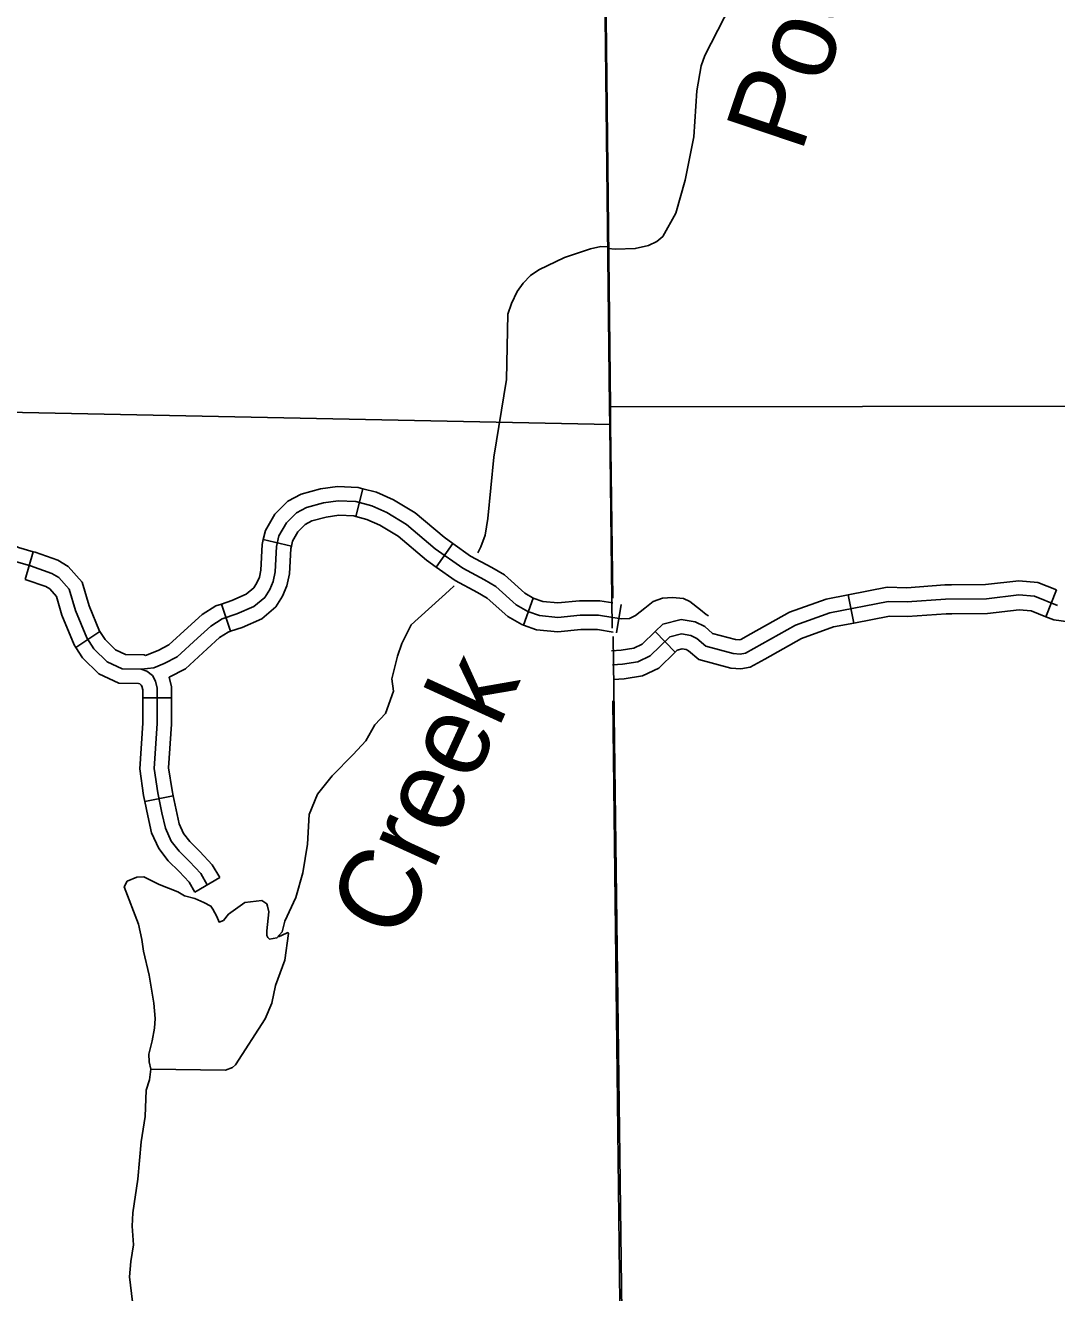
# Model space of a CAD drawing. Extents: x 1373862 to 1376999, y 1168398 to 1170455.
# Drawn here: x 1375499.6 to 1375607, y 1169230.9 to 1169362.9 of the extents above; entities that cross this region are included whole.
import ezdxf

# ---------------------------------------------------------------- set-up
doc = ezdxf.new("R2010")
doc.units = 0
for name, color, linetype in [('Level 2', 7, 'Continuous'), ('Level 32', 7, 'Continuous'), ('Level 35', 7, 'Continuous'), ('Level 45', 7, 'Continuous'), ('Level 5', 7, 'Continuous')]:
    doc.layers.add(name, color=color, linetype=linetype)

msp = doc.modelspace()

# ---------------------------------------------------------------- linework, layer by layer
at = {"layer": 'Level 2'}
for points in [[(1375559.39, 1169426.01), (1375560.53, 1169323.17), (1375560.52, 1169321.29), (1375560.75, 1169303.22)], [(1375559.85, 1169373.12), (1375560.43, 1169323.13), (1375560.44, 1169321.15), (1375560.68, 1169300.07)], [(1375560.8, 1169299.22), (1375561.85, 1169218.06), (1375561.86, 1169216.25), (1375562.18, 1169170.5)], [(1375560.77, 1169292.5), (1375561.64, 1169217.86), (1375561.7, 1169216.02)]]:
    msp.add_lwpolyline(points, dxfattribs=at)
at = {"layer": 'Level 32'}
for p, q in [((1375533.99, 1169311.71), (1375534.75, 1169314.61)), ((1375527.29, 1169308.64), (1375524.37, 1169309.31)), ((1375542.38, 1169306.45), (1375544.12, 1169308.89)), ((1375500.42, 1169308.04), (1375499.59, 1169305.16)), ((1375551.47, 1169300.39), (1375552.48, 1169303.21)), ((1375520.96, 1169299.76), (1375520.01, 1169302.6)), ((1375561.64, 1169302.56), (1375561.16, 1169299.6)), ((1375507.36, 1169299.72), (1375504.84, 1169298.08)), ((1375514.81, 1169292.84), (1375511.81, 1169292.84)), ((1375514.98, 1169282.63), (1375512.04, 1169282.02)), ((1375519.83, 1169274.12), (1375517.25, 1169272.59))]:
    msp.add_line(p, q, dxfattribs=at)
for points in [[(1375524.37, 1169309.31), (1375524.59, 1169310.26), (1375525.58, 1169311.97), (1375526.91, 1169313.3), (1375528.3, 1169314.05), (1375530.33, 1169314.6), (1375532.08, 1169314.85), (1375534.24, 1169314.75), (1375534.75, 1169314.61)], [(1375534.75, 1169314.61), (1375536.16, 1169314.24), (1375537.91, 1169313.46), (1375540.17, 1169312.1), (1375543.2, 1169309.55), (1375544.12, 1169308.89)], [(1375511.66, 1169295.81), (1375512.96, 1169295.97), (1375514.05, 1169296.4), (1375515.39, 1169297.1), (1375517.51, 1169299.05), (1375518.9, 1169300.3), (1375520.07, 1169301.04), (1375521.62, 1169301.56), (1375523.4, 1169302.34), (1375524.53, 1169303.29), (1375525.05, 1169304.12), (1375525.39, 1169304.94), (1375525.61, 1169305.94), (1375525.74, 1169308.58), (1375526, 1169309.7), (1375526.78, 1169311.05), (1375527.82, 1169312.09), (1375528.86, 1169312.65), (1375530.63, 1169313.13), (1375532.15, 1169313.34), (1375534.01, 1169313.26), (1375535.66, 1169312.82), (1375537.22, 1169312.13), (1375539.29, 1169310.87), (1375542.28, 1169308.36), (1375545.14, 1169306.33), (1375547.41, 1169305.11), (1375548.58, 1169304.42), (1375550.71, 1169302.51), (1375551.92, 1169301.82), (1375553.13, 1169301.39), (1375555.04, 1169301.21), (1375557.37, 1169301.43), (1375559.28, 1169301.43), (1375560.78, 1169301.18)], [(1375500.42, 1169308.04), (1375498.88, 1169308.48), (1375495.38, 1169310.25), (1375491.76, 1169311.36), (1375490.89, 1169311.8)], [(1375527.29, 1169308.64), (1375527.41, 1169309.15), (1375527.98, 1169310.13), (1375528.72, 1169310.87), (1375529.42, 1169311.25), (1375530.93, 1169311.66), (1375532.22, 1169311.84), (1375533.78, 1169311.77), (1375533.99, 1169311.71)], [(1375533.99, 1169311.71), (1375535.16, 1169311.4), (1375536.52, 1169310.8), (1375538.42, 1169309.65), (1375541.36, 1169307.17), (1375542.38, 1169306.45)], [(1375520.01, 1169302.6), (1375521.08, 1169302.96), (1375522.6, 1169303.62), (1375523.38, 1169304.29), (1375523.71, 1169304.81), (1375523.96, 1169305.39), (1375524.12, 1169306.13), (1375524.25, 1169308.79), (1375524.37, 1169309.31)], [(1375520.96, 1169299.76), (1375522.16, 1169300.16), (1375524.2, 1169301.05), (1375525.67, 1169302.3), (1375526.38, 1169303.42), (1375526.83, 1169304.48), (1375527.1, 1169305.74), (1375527.23, 1169308.37), (1375527.29, 1169308.64)], [(1375544.12, 1169308.89), (1375545.93, 1169307.6), (1375548.15, 1169306.42), (1375549.48, 1169305.63), (1375551.59, 1169303.73), (1375552.55, 1169303.19), (1375552.48, 1169303.21)], [(1375507.36, 1169299.72), (1375507.33, 1169299.76), (1375506.24, 1169302.42), (1375505.52, 1169304.88), (1375504.05, 1169306.52), (1375502.99, 1169307.15), (1375500.6, 1169307.99), (1375500.42, 1169308.04)], [(1375518.54, 1169273.35), (1375517.85, 1169274.52), (1375516.68, 1169275.78), (1375515.6, 1169276.86), (1375514.77, 1169277.9), (1375514.17, 1169279.24), (1375513.82, 1169280.85), (1375513.39, 1169282.93), (1375513.01, 1169285.48), (1375513.31, 1169290.14), (1375513.31, 1169293.82), (1375513.14, 1169294.56), (1375512.83, 1169295.16), (1375512.23, 1169295.6), (1375511.66, 1169295.81), (1375509.67, 1169295.86), (1375508.11, 1169296.59), (1375506.73, 1169297.94), (1375505.99, 1169299.06), (1375504.82, 1169301.92), (1375504.17, 1169304.13), (1375503.09, 1169305.35), (1375502.35, 1169305.78), (1375500.14, 1169306.56), (1375498.33, 1169307.08)], [(1375542.38, 1169306.45), (1375544.35, 1169305.05), (1375546.68, 1169303.8), (1375547.69, 1169303.2), (1375549.82, 1169301.29), (1375551.29, 1169300.45), (1375551.47, 1169300.39)], [(1375504.84, 1169298.08), (1375504.66, 1169298.36), (1375503.4, 1169301.43), (1375502.83, 1169303.39), (1375502.13, 1169304.17), (1375501.72, 1169304.41), (1375499.69, 1169305.13), (1375499.59, 1169305.16)], [(1375552.48, 1169303.21), (1375553.46, 1169302.86), (1375555.03, 1169302.72), (1375557.31, 1169302.93), (1375559.4, 1169302.93), (1375560.76, 1169302.71)], [(1375570.72, 1169301.37), (1375570.49, 1169301.52), (1375569.88, 1169301.99), (1375568.8, 1169302.86), (1375568.11, 1169303.16), (1375566.99, 1169303.29), (1375565.95, 1169303.21), (1375564.95, 1169302.86), (1375564.09, 1169302.17), (1375563.13, 1169301.39), (1375562.49, 1169301.08), (1375561.66, 1169301.04), (1375560.78, 1169301.18)], [(1375512.12, 1169297.25), (1375513.42, 1169297.77), (1375514.52, 1169298.34), (1375516.5, 1169300.15), (1375517.99, 1169301.5), (1375519.42, 1169302.4), (1375520.01, 1169302.6)], [(1375512.12, 1169297.25), (1375511.96, 1169297.31), (1375510.02, 1169297.35), (1375508.98, 1169297.84), (1375507.89, 1169298.9), (1375507.36, 1169299.72)], [(1375514.58, 1169294.99), (1375516.26, 1169295.86), (1375518.52, 1169297.94), (1375519.81, 1169299.1), (1375520.71, 1169299.67), (1375520.96, 1169299.76)], [(1375551.47, 1169300.39), (1375552.81, 1169299.91), (1375555.04, 1169299.71), (1375557.44, 1169299.93), (1375559.16, 1169299.93), (1375560.8, 1169299.66)], [(1375511.81, 1169292.84), (1375511.81, 1169293.65), (1375511.72, 1169294.04), (1375511.66, 1169294.16), (1375511.51, 1169294.27), (1375511.37, 1169294.32), (1375509.32, 1169294.36), (1375507.25, 1169295.34), (1375505.56, 1169296.98), (1375504.84, 1169298.08)], [(1375514.81, 1169292.84), (1375514.81, 1169293.99), (1375514.58, 1169294.99)], [(1375512.04, 1169282.02), (1375511.91, 1169282.66), (1375511.5, 1169285.42), (1375511.81, 1169290.19), (1375511.81, 1169292.84)], [(1375514.98, 1169282.63), (1375514.87, 1169283.19), (1375514.51, 1169285.55), (1375514.81, 1169290.09), (1375514.81, 1169292.84)], [(1375519.83, 1169274.12), (1375519.06, 1169275.43), (1375517.76, 1169276.82), (1375516.72, 1169277.86), (1375516.06, 1169278.69), (1375515.6, 1169279.72), (1375515.29, 1169281.16), (1375514.98, 1169282.63)], [(1375517.25, 1169272.59), (1375516.64, 1169273.62), (1375515.6, 1169274.74), (1375514.47, 1169275.86), (1375513.48, 1169277.12), (1375512.73, 1169278.77), (1375512.35, 1169280.54), (1375512.04, 1169282.02)]]:
    msp.add_lwpolyline(points, dxfattribs=at)
at = {"layer": 'Level 35'}
for points in [[(1375573.72, 1169366.31), (1375570.34, 1169359.74), (1375569.96, 1169358.65), (1375569.51, 1169356.05), (1375569.2, 1169351.25), (1375568.31, 1169346.75), (1375567.31, 1169343.32), (1375565.98, 1169340.89), (1375565.35, 1169340.35), (1375564.47, 1169339.95), (1375563.1, 1169339.62), (1375561.03, 1169339.55), (1375560.24, 1169339.61)], [(1375560.34, 1169339.79), (1375559.53, 1169339.85), (1375558.43, 1169339.6), (1375555.75, 1169338.7), (1375553.05, 1169337.4), (1375552.18, 1169336.8), (1375551.44, 1169336), (1375550.81, 1169335.14), (1375550.2, 1169333.89), (1375549.82, 1169332.78), (1375549.69, 1169325.99), (1375548.37, 1169317.9), (1375547.74, 1169311.51), (1375547.46, 1169309.78), (1375547.03, 1169308.55), (1375546.71, 1169307.92)], [(1375544.23, 1169304.51), (1375543.74, 1169304), (1375539.75, 1169300.42), (1375538.79, 1169298.48), (1375538.35, 1169297.16), (1375537.76, 1169294.82), (1375537.93, 1169293.51), (1375537.1, 1169291.18), (1375536, 1169290.01), (1375535.04, 1169288.35), (1375533.73, 1169286.91), (1375531.53, 1169284.71), (1375530.02, 1169282.78), (1375529.13, 1169280.67), (1375528.96, 1169277.6), (1375528.47, 1169274.6), (1375527.74, 1169272.02), (1375526.61, 1169269.57), (1375526.35, 1169268.44), (1375525.79, 1169267.82), (1375525.03, 1169267.71), (1375524.84, 1169267.86), (1375524.74, 1169268.06), (1375524.75, 1169268.56), (1375524.93, 1169270.55), (1375524.81, 1169271.13), (1375524.73, 1169271.37), (1375524.22, 1169271.72), (1375522.44, 1169271.52), (1375520.76, 1169270.3), (1375520.21, 1169269.63), (1375519.76, 1169269.48), (1375519.52, 1169270.05), (1375519.1, 1169270.81), (1375518.91, 1169271.14), (1375518.18, 1169271.5), (1375517.25, 1169271.93), (1375516.18, 1169272.21), (1375515.46, 1169272.63), (1375513.53, 1169273.39), (1375511.93, 1169274.18), (1375511.19, 1169274.14), (1375510.2, 1169273.72), (1375509.87, 1169273.15), (1375511.36, 1169269.25), (1375511.72, 1169267.65), (1375511.9, 1169266.46), (1375512.5, 1169263.96), (1375512.96, 1169261.04), (1375513.1, 1169259.44), (1375513.04, 1169258.42), (1375512.81, 1169257.09), (1375512.44, 1169255.72), (1375512.48, 1169254.92), (1375512.67, 1169254.14), (1375512.52, 1169253.05), (1375512.18, 1169251.98), (1375512.08, 1169249.21), (1375511.64, 1169246.59), (1375511.32, 1169242.71), (1375510.78, 1169239.19), (1375510.71, 1169237.81), (1375510.87, 1169235.85), (1375510.57, 1169234.11), (1375510.42, 1169232.53), (1375510.74, 1169229.93)], [(1375525.95, 1169267.93), (1375526.78, 1169268.33), (1375526.92, 1169268.37), (1375527, 1169268.29), (1375526.6, 1169265.49), (1375525.64, 1169262.87), (1375525.25, 1169261.03), (1375524.55, 1169259.39), (1375521.47, 1169254.61), (1375521.15, 1169254.34), (1375520.42, 1169254.05), (1375512.67, 1169254.14)]]:
    msp.add_lwpolyline(points, dxfattribs=at)
at = {"layer": 'Level 45'}
for p, q in [((1375585.28, 1169303.56), (1375585.85, 1169300.62)), ((1375606.98, 1169304.06), (1375605.87, 1169301.27)), ((1375565.18, 1169299.74), (1375567.27, 1169297.58))]:
    msp.add_line(p, q, dxfattribs=at)
for points in [[(1375596.03, 1169304.59), (1375595.35, 1169304.58), (1375591.38, 1169304.3), (1375589.33, 1169304.34), (1375585.28, 1169303.56)], [(1375606.98, 1169304.06), (1375605.02, 1169304.84), (1375603.03, 1169305.03), (1375599.58, 1169304.62), (1375596.03, 1169304.59)], [(1375607.08, 1169302.44), (1375604.67, 1169303.4), (1375603.05, 1169303.55), (1375599.68, 1169303.14), (1375595.41, 1169303.11), (1375591.42, 1169302.83), (1375589.45, 1169302.86), (1375583.35, 1169301.69), (1375579.78, 1169300.41), (1375574.57, 1169297.48), (1375574.03, 1169297.39), (1375573.31, 1169297.45), (1375570.45, 1169298.2), (1375569.51, 1169299.01), (1375568.89, 1169299.31), (1375567.93, 1169299.48), (1375566.7, 1169299.17), (1375564.67, 1169297.19), (1375563.38, 1169296.58), (1375561.78, 1169296.33), (1375560.73, 1169296.26)], [(1375585.28, 1169303.56), (1375582.97, 1169303.12), (1375579.17, 1169301.76), (1375575.12, 1169299.48)], [(1375605.87, 1169301.27), (1375604.31, 1169301.9), (1375603.07, 1169302.01), (1375599.77, 1169301.62), (1375596.05, 1169301.59)], [(1375575.12, 1169299.48), (1375574.08, 1169298.89), (1375573.97, 1169298.87), (1375573.55, 1169298.9), (1375571.15, 1169299.54), (1375570.33, 1169300.25), (1375569.35, 1169300.73), (1375567.87, 1169300.98), (1375565.96, 1169300.49), (1375565.18, 1169299.74)], [(1375585.85, 1169300.62), (1375583.76, 1169300.22), (1375580.42, 1169299.02), (1375576.6, 1169296.87)], [(1375596.05, 1169301.59), (1375595.47, 1169301.58), (1375591.46, 1169301.3), (1375589.59, 1169301.33), (1375585.85, 1169300.62)], [(1375617.01, 1169300.21), (1375616.02, 1169300.14), (1375611.77, 1169300.27), (1375606.69, 1169300.95), (1375605.87, 1169301.27)], [(1375565.18, 1169299.74), (1375563.82, 1169298.42), (1375562.94, 1169298), (1375561.62, 1169297.79), (1375560.63, 1169297.73)], [(1375576.6, 1169296.87), (1375575.08, 1169296.01), (1375574.09, 1169295.86), (1375573.06, 1169295.93), (1375569.72, 1169296.82), (1375568.66, 1169297.72), (1375568.41, 1169297.85), (1375567.99, 1169297.92), (1375567.48, 1169297.79), (1375567.27, 1169297.58)], [(1375567.27, 1169297.58), (1375565.55, 1169295.92), (1375563.84, 1169295.11), (1375561.95, 1169294.81), (1375560.83, 1169294.73)]]:
    msp.add_lwpolyline(points, dxfattribs=at)
at = {"layer": 'Level 5'}
for points in [[(1375463.56, 1169323.26), (1375560.52, 1169321.29)], [(1375706.99, 1169323.42), (1375665.83, 1169323.26), (1375560.41, 1169323.15)]]:
    msp.add_lwpolyline(points, dxfattribs=at)

# ---------------------------------------------------------------- texts
at = {"layer": 'Level 35'}
for s, height, rotation, p in [('Poe', 8.44, 71.354, (1375580.37, 1169349.44)), ('Creek', 8.448, 65.3854, (1375538.64, 1169267.29))]:
    msp.add_text(s, height=height, rotation=rotation, dxfattribs=at).set_placement(p)

doc.saveas('drawing.dxf')
